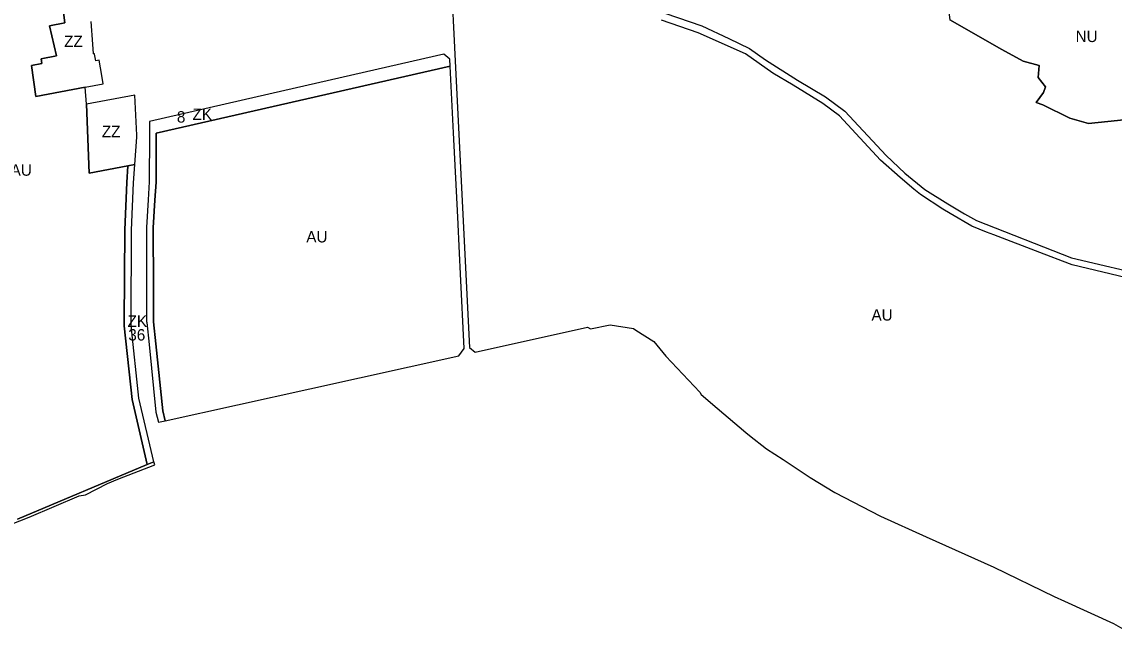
# Model space of a CAD drawing. Extents: x -522079 to -518833, y -1142398 to -1139961.
# Drawn here: x -520386 to -519428, y -1141866 to -1141332 of the extents above; entities that cross this region are included whole.
import ezdxf

# ---------------------------------------------------------------- set-up
doc = ezdxf.new("R2010")
doc.units = 0
for name, color, linetype in [('90640013', 7, 'Continuous'), ('90670013', 7, 'Continuous'), ('90710023', 7, 'Continuous'), ('90730013', 7, 'Continuous'), ('90750013', 7, 'Continuous'), ('90770013', 7, 'Continuous'), ('ID_navrh', 7, 'Continuous')]:
    doc.layers.add(name, color=color, linetype=linetype)

msp = doc.modelspace()

# ---------------------------------------------------------------- linework, layer by layer
at = {"layer": '90640013'}
msp.add_lwpolyline([(-520396.49, -1141772.96), (-520379.93, -1141766.64), (-520336.12, -1141747.68), (-520330.69, -1141747.06), (-520311.37, -1141736.89), (-520302.33, -1141733.12), (-520269.8, -1141720.57), (-520270.75, -1141718.04), (-520276.36, -1141720.39), (-520390.37, -1141768.15)], dxfattribs=at)
at = {"layer": '90670013'}
msp.add_lwpolyline([(-520353.1, -1141297.63), (-520348.74, -1141332.58), (-520362.13, -1141335.31), (-520355.94, -1141361.7), (-520369.53, -1141364.42), (-520368.84, -1141368.35), (-520378.01, -1141370.07), (-520374.09, -1141397.41), (-520330.86, -1141389.2), (-520315.07, -1141386.2), (-520316.31, -1141378.99), (-520318.64, -1141365.48), (-520321.57, -1141366.05), (-520322.7, -1141360.25), (-520322.8, -1141359.78), (-520323.6, -1141359.93), (-520324.17, -1141351.52), (-520325.53, -1141331.62)], dxfattribs=at)
msp.add_lwpolyline([(-520293.35, -1141458.14), (-520287.25, -1141456.97), (-520285.53, -1141433.12), (-520285.62, -1141431.18), (-520287.2, -1141396.11), (-520329.77, -1141404.14), (-520327.5, -1141464.71)], close=True, dxfattribs=at)
at = {"layer": '90710023'}
for points in [[(-520260.66, -1141681.95), (-520260.68, -1141681.85), (-520262.8, -1141673.2), (-520268.87, -1141614.33), (-520270.85, -1141595.16), (-520270.93, -1141594.41), (-520271.03, -1141563.69), (-520271.2, -1141512.61), (-520269.68, -1141488.31), (-520268.69, -1141472.55), (-520268.47, -1141429.64), (-520010.61, -1141370.65), (-520010.91, -1141364.55), (-520016.19, -1141360.33), (-520155.8, -1141392.1), (-520274.28, -1141419.2), (-520274.48, -1141431.01), (-520274.69, -1141472.35), (-520275.67, -1141487.93), (-520277.2, -1141512.43), (-520277.03, -1141563.71), (-520276.93, -1141594.74), (-520276.82, -1141595.78), (-520274.84, -1141614.95), (-520268.73, -1141674.23), (-520266.52, -1141683.24)], [(-520293.35, -1141458.14), (-520294.41, -1141472.89), (-520296.19, -1141514.43), (-520296.52, -1141595.69), (-520296.53, -1141598.74), (-520289.6, -1141663.22), (-520276.36, -1141720.39), (-520270.75, -1141718.04), (-520283.67, -1141662.22), (-520290.53, -1141598.43), (-520290.52, -1141595.71), (-520290.19, -1141514.57), (-520288.42, -1141473.23), (-520287.25, -1141456.97)]]:
    msp.add_lwpolyline(points, close=True, dxfattribs=at)
at = {"layer": '90730013'}
msp.add_lwpolyline([(-519512.96, -1141256.69), (-519524.47, -1141258.63), (-519555.19, -1141299.24), (-519560.68, -1141302.79), (-519567.64, -1141300.94), (-519572.4, -1141313.2), (-519574.58, -1141312.28), (-519572.25, -1141330.06), (-519526.67, -1141356.01), (-519507.9, -1141366.28), (-519493.9, -1141370.24), (-519494.92, -1141380.6), (-519488.36, -1141388.76), (-519489.99, -1141393.96), (-519496.45, -1141402.69), (-519490.7, -1141404.57), (-519466.91, -1141416.21), (-519450.75, -1141420.94), (-519402.53, -1141416.1)], dxfattribs=at)
at = {"layer": '90750013'}
for points in [[(-520010.89, -1141271.2), (-520005.29, -1141383.92), (-519993.67, -1141617.6), (-519988.83, -1141621.62), (-519890.16, -1141599.67), (-519887.54, -1141601.15), (-519870.13, -1141597.7), (-519849.83, -1141601.06), (-519847.75, -1141602.33), (-519831.88, -1141612.23), (-519821.3, -1141625.26), (-519791.74, -1141656.89), (-519790.37, -1141658.77), (-519776.39, -1141670.73), (-519751.14, -1141692.22), (-519747.91, -1141694.83), (-519733.23, -1141706.57), (-519718.63, -1141715.98), (-519694.8, -1141731.79), (-519673.22, -1141744.78), (-519633.06, -1141765.56), (-519593.13, -1141783.65), (-519533.59, -1141810.27), (-519480.84, -1141836.08), (-519471.59, -1141840.28), (-519428.71, -1141859.77), (-519418.41, -1141865.69)], [(-520390.37, -1141768.15), (-520276.36, -1141720.39), (-520289.6, -1141663.22), (-520296.53, -1141598.74), (-520296.52, -1141595.69), (-520296.19, -1141514.43), (-520294.41, -1141472.89), (-520293.35, -1141458.14), (-520327.5, -1141464.71), (-520329.77, -1141404.14), (-520330.86, -1141389.2), (-520374.09, -1141397.41), (-520378.01, -1141370.07), (-520368.84, -1141368.35), (-520369.53, -1141364.42), (-520355.94, -1141361.7), (-520362.13, -1141335.31), (-520348.74, -1141332.58), (-520353.1, -1141297.63)], [(-519397.82, -1141561.07), (-519464.89, -1141545.09), (-519467.42, -1141544.19), (-519493.41, -1141534.2), (-519533.7, -1141518.85), (-519536.79, -1141517.61), (-519539.97, -1141516.35), (-519553.06, -1141511.15), (-519571.87, -1141500.11), (-519578.53, -1141496.09), (-519598.08, -1141483.22), (-519603.81, -1141478.65), (-519615.77, -1141468.45), (-519633.24, -1141453.23), (-519668.96, -1141414.21), (-519683.78, -1141403.39), (-519709.78, -1141387.41), (-519727.64, -1141376.95), (-519751.63, -1141360.04), (-519793.08, -1141341.43), (-519825.24, -1141330.38)]]:
    msp.add_lwpolyline(points, dxfattribs=at)
msp.add_lwpolyline([(-520260.66, -1141681.95), (-520133.69, -1141653.91), (-520003.08, -1141624.98), (-519998.35, -1141618.37), (-520001.59, -1141552.99), (-520002.49, -1141534.74), (-520004.05, -1141503.1), (-520007.71, -1141429.14), (-520010.61, -1141370.65), (-520268.47, -1141429.64), (-520268.69, -1141472.55), (-520269.68, -1141488.31), (-520271.2, -1141512.61), (-520271.03, -1141563.69), (-520270.93, -1141594.41), (-520270.85, -1141595.16), (-520268.87, -1141614.33), (-520262.8, -1141673.2), (-520260.68, -1141681.85)], close=True, dxfattribs=at)
at = {"layer": '90770013'}
for points in [[(-519864.09, -1141309.46), (-519789.84, -1141335.36), (-519766.26, -1141346.58), (-519748.09, -1141355.2), (-519733.94, -1141365.09), (-519705.92, -1141383), (-519681.23, -1141397.53), (-519664.49, -1141410.15), (-519628.16, -1141449.15), (-519611.87, -1141464.55), (-519594.12, -1141478.91), (-519574.1, -1141491.51), (-519559.27, -1141500.34), (-519548.85, -1141506.03), (-519465.6, -1141538.79), (-519393.2, -1141555.81)], [(-519402.53, -1141416.1), (-519450.75, -1141420.94), (-519466.91, -1141416.21), (-519490.7, -1141404.57), (-519496.45, -1141402.69), (-519489.99, -1141393.96), (-519488.36, -1141388.76), (-519494.92, -1141380.6), (-519493.9, -1141370.24), (-519507.9, -1141366.28), (-519526.67, -1141356.01), (-519572.25, -1141330.06)]]:
    msp.add_lwpolyline(points, dxfattribs=at)

# ---------------------------------------------------------------- texts
at = {"layer": '90670013'}
for p in [(-520349.37, -1141353.97), (-520316.26, -1141433.07)]:
    msp.add_text('ZZ', height=10, rotation=360, dxfattribs=at).set_placement(p)
at = {"layer": '90710023'}
for p in [(-520236.68, -1141417.93), (-520293.68, -1141599.5)]:
    msp.add_text('ZK', height=10, rotation=0, dxfattribs=at).set_placement(p)
at = {"layer": '90730013'}
msp.add_text('NU', height=10, rotation=360, dxfattribs=at).set_placement((-519461.93, -1141349.56))
at = {"layer": '90750013'}
for rotation, p in [(0, (-520396.22, -1141466.89)), (360, (-520136.86, -1141525.4)), (360, (-519641.01, -1141594.01))]:
    msp.add_text('AU', height=10, rotation=rotation, dxfattribs=at).set_placement(p)
at = {"layer": 'ID_navrh'}
for s, rotation, p in [('8', 0, (-520250.39, -1141420.2)), ('36', 360, (-520293.01, -1141611.5))]:
    msp.add_text(s, height=10, rotation=rotation, dxfattribs=at).set_placement(p)

doc.saveas('drawing.dxf')
